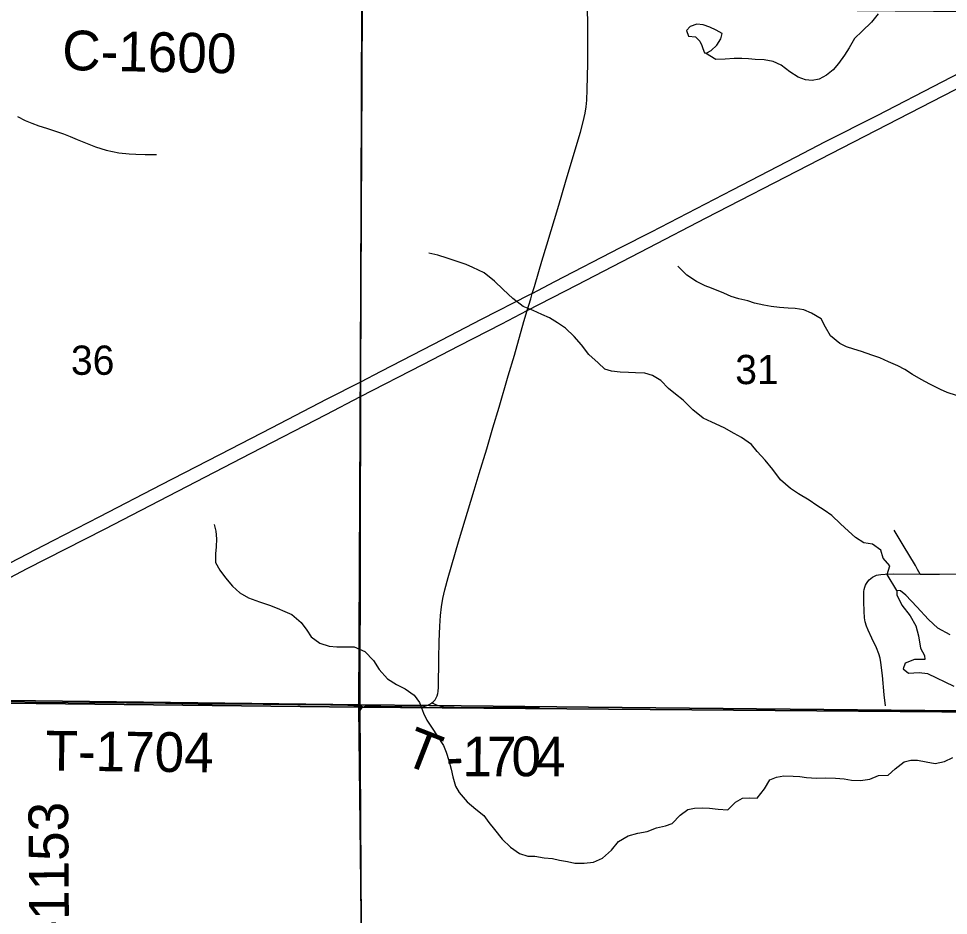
# Model space of a CAD drawing. Extents: x 1874609 to 2204689, y 815661 to 1281160.
# Drawn here: x 2010253 to 2017280, y 1023652 to 1030428 of the extents above; entities that cross this region are included whole.
import ezdxf

# ---------------------------------------------------------------- set-up
doc = ezdxf.new("R2010")
doc.units = 0
for name, color, linetype in [('GM_X_County_Road', 7, 'Continuous'), ('GM_X_County_Road_Text', 7, 'Continuous'), ('GM_X_Interstate_Route', 7, 'Continuous'), ('GM_X_Minor_Lake', 7, 'Continuous'), ('GM_X_Minor_River', 7, 'Continuous'), ('GM_X_Section', 7, 'Continuous'), ('GM_X_Section_Text', 7, 'Continuous'), ('GM_X_Township', 7, 'Continuous'), ('GM_X_Township_Road', 7, 'Continuous'), ('GM_X_Township_Road_Text', 7, 'Continuous')]:
    doc.layers.add(name, color=color, linetype=linetype)

msp = doc.modelspace()

# ---------------------------------------------------------------- linework, layer by layer
at = {"layer": 'GM_X_County_Road'}
for points in [[(2014150.8, 1028403.9), (2014156, 1028421.4), (2014207.7, 1028594.3), (2014246.2, 1028719.7), (2014335.1, 1029018.6), (2014385.5, 1029191.9), (2014452.6, 1029411.5), (2014498.8, 1029569), (2014519.9, 1029648.4), (2014534, 1029712.7), (2014541.5, 1029761.7), (2014546.4, 1029810.8), (2014550.7, 1029893), (2014554.7, 1030089.8), (2014555.1, 1030237.5), (2014554.7, 1030368.4), (2014553, 1030522.7)], [(2013376.8, 1025258.1), (2013389.3, 1025268), (2013400.7, 1025281), (2013409.8, 1025295.5), (2013416.6, 1025311), (2013421.5, 1025327.3), (2013424.6, 1025343.8), (2013427.5, 1025377.1), (2013429.5, 1025590.5), (2013430.8, 1025721.6), (2013435.2, 1025836.2), (2013440.8, 1025917.8), (2013448.4, 1025982.7), (2013459.2, 1026047.1), (2013473.5, 1026110.9), (2013498.9, 1026205.8), (2013577.7, 1026473.3), (2013696.7, 1026865.8), (2013734.3, 1026989.8), (2013790.6, 1027178.3), (2013836.1, 1027335.9), (2013884, 1027492.7), (2013953, 1027729), (2013999.9, 1027886.2), (2014072, 1028138.5), (2014096.4, 1028221.4), (2014122.9, 1028311.5), (2014135.1, 1028352.1), (2014150.8, 1028403.9)], [(2012846.1, 1023532.4), (2012844.1, 1023650.5), (2012841.4, 1023863.8), (2012834.4, 1024421.5), (2012834.6, 1024519.9), (2012832.2, 1024634.9), (2012831.3, 1024716.8), (2012829.1, 1024913.8), (2012828.9, 1024929.4), (2012829.1, 1024977.7), (2012829.3, 1025035), (2012829.5, 1025110.4), (2012829.6, 1025143.3), (2012829.7, 1025155.8), (2012830.1, 1025168), (2012830.8, 1025177.8), (2012832.8, 1025190), (2012834.8, 1025197.9), (2012838.7, 1025207.4), (2012843.4, 1025214.1), (2012850.5, 1025221.6), (2012857.7, 1025226.3)], [(2012857.7, 1025226.3), (2012866.3, 1025230.2), (2012875.8, 1025233), (2012891.5, 1025235.4), (2012908.5, 1025235.1), (2012989.4, 1025233.6), (2013148.3, 1025229.6), (2013264.6, 1025226.6), (2013297.7, 1025228.8), (2013314.3, 1025231.3), (2013330.7, 1025235.1), (2013346.7, 1025240.8), (2013361.8, 1025248.6), (2013375.9, 1025257.4), (2013376.8, 1025258.1)]]:
    msp.add_lwpolyline(points, dxfattribs=at)
at = {"layer": 'GM_X_Interstate_Route'}
for points in [[(2010190.2, 1026315.5), (2010515.5, 1026485.5), (2010865.9, 1026665.1), (2011331.9, 1026907), (2011857.2, 1027177.1), (2012163.3, 1027335.4), (2012586, 1027553.9), (2012838.3, 1027684.6), (2012993.9, 1027765.2), (2013387.8, 1027968), (2013751.6, 1028157.3), (2014117.3, 1028342.8), (2014135.1, 1028352.1), (2014306.6, 1028441.3), (2014801.7, 1028697.7), (2015035.9, 1028816.3), (2015647.3, 1029134), (2016128, 1029383), (2016346.7, 1029495.7), (2016741.2, 1029696.9), (2017236.4, 1029953.7), (2017761.2, 1030224.5)], [(2010189.6, 1026203.8), (2010317.3, 1026271.9), (2010901.7, 1026571), (2012009.6, 1027143.6), (2012578.2, 1027437.4), (2012838, 1027571.5), (2013307.4, 1027813.6), (2013584.1, 1027957.2), (2013905.1, 1028122.6), (2014096.4, 1028221.4), (2014473.5, 1028416.2), (2015012.5, 1028695.3), (2015449.7, 1028921.5), (2016222.7, 1029319.6), (2017753.6, 1030109.5)]]:
    msp.add_lwpolyline(points, dxfattribs=at)
at = {"layer": 'GM_X_Minor_Lake'}
for points in [[(2015453.4, 1030169.6), (2015487.5, 1030187.5), (2015529.8, 1030227.5), (2015560, 1030275.6), (2015570.1, 1030315.7), (2015524.1, 1030341.9), (2015478, 1030364.1), (2015425.9, 1030380.4), (2015379.8, 1030386.5), (2015327.6, 1030368.7), (2015299.4, 1030338.7), (2015315.3, 1030294.5), (2015367.5, 1030290.3), (2015401.5, 1030258.1), (2015415.4, 1030225.9), (2015423.4, 1030201.8)], [(2015423.4, 1030201.8), (2015436.4, 1030169.4), (2015445.8, 1030167.7), (2015453.4, 1030169.6)], [(2017292.7, 1025772.4), (2017198.7, 1025822.9), (2017128.8, 1025887.4), (2017040.9, 1025982.1), (2016959, 1026072.7), (2016917, 1026103), (2016889, 1026107.1), (2016888.9, 1026073), (2016926.7, 1025996.7), (2016990.5, 1025914.1), (2017032.4, 1025839.7), (2017054.1, 1025763.4), (2017069.8, 1025671), (2017099.7, 1025616.7), (2017101.6, 1025584.7), (2017023.4, 1025585), (2016953.2, 1025557.2), (2016939, 1025515.2), (2016979, 1025480.9), (2017059.2, 1025486.5), (2017121.3, 1025480.2), (2017321.4, 1025385.1)]]:
    msp.add_lwpolyline(points, dxfattribs=at)
at = {"layer": 'GM_X_Minor_River'}
for points in [[(2016748, 1030464.1), (2016699.6, 1030400), (2016627.2, 1030332.1), (2016570.9, 1030278.1), (2016528.6, 1030208), (2016494.3, 1030151.9), (2016450, 1030089.9), (2016409.8, 1030039.9), (2016359.5, 1029999.9), (2016303.3, 1029970), (2016251.1, 1029960.2), (2016200.9, 1029964.4), (2016144.8, 1029986.6), (2016080.8, 1030027), (2016016.7, 1030075.4), (2015954.6, 1030103.7), (2015886.5, 1030115.9), (2015820.3, 1030120.2), (2015768.2, 1030124.4), (2015718, 1030126.5), (2015661.9, 1030126.8), (2015591.6, 1030121), (2015523.4, 1030119.2), (2015444.5, 1030167.9)], [(2010244.5, 1029687.2), (2010302.6, 1029658.8), (2010352.6, 1029638.6), (2010406.6, 1029618.3), (2010464.7, 1029600), (2010532.8, 1029577.6), (2010592.9, 1029557.3), (2010642.9, 1029537), (2010694.9, 1029514.7), (2010745, 1029494.4), (2010833.1, 1029459.9), (2010915.2, 1029433.5), (2011011.3, 1029413), (2011089.5, 1029406.6), (2011139.6, 1029404.4), (2011209.7, 1029402.1), (2011295.9, 1029401.7)], [(2016889, 1026107.1), (2016817.3, 1026227.8), (2016837.5, 1026293.9), (2016787.6, 1026350.3), (2016769.8, 1026412.6), (2016705.8, 1026457), (2016641.7, 1026467.3), (2016577.7, 1026507.7), (2016523.8, 1026556.1), (2016463.8, 1026610.5), (2016399.9, 1026673), (2016341.9, 1026713.4), (2016285.9, 1026749.7), (2016227.9, 1026788.1), (2016147.9, 1026836.6), (2016085.9, 1026877), (2016010, 1026943.5), (2015954.1, 1027020), (2015894.2, 1027090.5), (2015834.3, 1027156.9), (2015792.4, 1027209.3), (2015716.4, 1027263.8), (2015660.4, 1027292.1), (2015584.4, 1027336.6), (2015492.3, 1027379.1), (2015426.3, 1027409.5), (2015348.3, 1027472), (2015274.4, 1027544.6), (2015218.5, 1027590.9), (2015164.5, 1027633.3), (2015106.6, 1027693.8), (2015042.6, 1027732.1), (2014986.5, 1027748.4), (2014916.3, 1027750.8), (2014862.2, 1027753), (2014798.1, 1027757.3), (2014734, 1027763.6), (2014683.9, 1027779.9), (2014632, 1027828.2), (2014562, 1027890.7), (2014508.2, 1027963.2), (2014450.3, 1028025.6), (2014386.3, 1028090.1), (2014326.3, 1028130.5), (2014264.3, 1028166.9), (2014206.3, 1028193.2), (2014142.2, 1028221.6), (2014066.2, 1028252), (2013988.2, 1028312.5), (2013914.3, 1028381.1), (2013848.4, 1028443.5), (2013770.4, 1028506.1), (2013686.4, 1028546.6), (2013634.3, 1028568.9), (2013560.2, 1028595.3), (2013492.2, 1028617.7), (2013420.1, 1028640), (2013354, 1028656.4)], [(2015376.2, 1028440.4), (2015302.1, 1028488.8), (2015236.1, 1028557.3)], [(2017341.4, 1027580.9), (2017271.3, 1027603.3), (2017219.2, 1027625.5), (2017139.1, 1027665.9), (2017075, 1027702.3), (2017008.9, 1027738.6), (2016950.8, 1027776.9), (2016898.8, 1027805.2), (2016826.6, 1027833.5), (2016760.5, 1027863.8), (2016700.4, 1027886.1), (2016622.3, 1027912.5), (2016564.2, 1027930.7), (2016510.1, 1027949), (2016460, 1027973.2), (2016387.9, 1028031.7), (2016352, 1028096), (2016318.1, 1028158.3), (2016244, 1028202.7), (2016187.9, 1028227), (2016121.8, 1028237.2), (2016067.6, 1028239.4), (2016003.4, 1028245.7), (2015941.3, 1028253.9), (2015885.2, 1028262.1), (2015815, 1028278.4), (2015762.9, 1028294.6), (2015696.8, 1028310.9), (2015638.6, 1028329.2), (2015582.5, 1028353.4), (2015490.4, 1028391.9), (2015440.3, 1028410.1), (2015376.2, 1028440.4)], [(2011730.9, 1026605.4), (2011742.8, 1026555.2), (2011748.6, 1026497), (2011746.4, 1026436.8), (2011740.2, 1026382.7), (2011741.9, 1026318.5), (2011773.8, 1026260.2), (2011817.7, 1026201.8), (2011869.6, 1026139.4), (2011925.5, 1026089), (2011991.6, 1026050.6), (2012073.6, 1026022.2), (2012149.7, 1025995.7), (2012207.8, 1025973.4), (2012265.8, 1025949.1), (2012317.9, 1025924.8), (2012387.8, 1025864.3), (2012431.7, 1025807.9), (2012463.6, 1025757.7), (2012529.6, 1025709.2), (2012599.6, 1025686.8), (2012657.8, 1025680.6), (2012788.1, 1025680), (2012870.1, 1025645.5), (2012934, 1025577), (2012977.9, 1025508.6), (2013039.8, 1025438.2), (2013109.8, 1025395.7), (2013173.8, 1025363.3), (2013241.8, 1025314.9), (2013281.7, 1025260.6), (2013313.5, 1025180.2), (2013337.3, 1025127.9), (2013377.2, 1025067.6), (2013417.1, 1025009.2), (2013462.9, 1024936.8), (2013484.8, 1024884.6), (2013504.6, 1024822.3), (2013522.4, 1024756), (2013534.2, 1024697.8), (2013554, 1024629.5), (2013581.9, 1024579.2), (2013643.8, 1024510.8), (2013707.8, 1024454.3), (2013767.7, 1024405.9), (2013807.6, 1024353.6), (2013849.5, 1024301.2), (2013907.4, 1024226.8), (2013969.4, 1024168.3), (2014037.3, 1024119.9), (2014101.4, 1024099.5), (2014153.5, 1024099.3), (2014223.6, 1024086.9), (2014287.8, 1024080.6), (2014341.8, 1024068.4), (2014401.9, 1024058.1), (2014456, 1024045.8), (2014526.2, 1024045.5), (2014598.4, 1024055.2), (2014666.6, 1024083), (2014733, 1024144.8), (2014787.4, 1024210.8), (2014859.7, 1024252.6), (2014931.9, 1024272.4), (2015004.1, 1024286.1), (2015074.4, 1024313.8), (2015142.6, 1024327.6), (2015192.8, 1024347.4), (2015253.2, 1024409.3), (2015311.4, 1024453.2), (2015361.6, 1024463), (2015423.7, 1024464.8), (2015473.8, 1024462.5), (2015540, 1024454.2), (2015612.1, 1024449.9), (2015670.5, 1024507.8), (2015722.7, 1024537.6), (2015774.8, 1024541.4), (2015834.9, 1024537.1), (2015889.3, 1024609.1), (2015929.7, 1024675.1), (2015979.9, 1024697), (2016036, 1024706.8), (2016106.2, 1024704.4), (2016156.3, 1024700.2), (2016206.4, 1024694), (2016282.5, 1024689.6), (2016352.7, 1024691.3), (2016426.8, 1024689), (2016493, 1024682.7), (2016547.1, 1024674.4), (2016615.2, 1024670.1), (2016685.4, 1024681.8), (2016751.7, 1024709.6), (2016823.8, 1024711.3), (2016878.1, 1024759.2), (2016944.5, 1024811), (2016996.6, 1024824.8), (2017046.8, 1024824.6), (2017110.9, 1024812.3), (2017179, 1024800)], [(2017179, 1024800), (2017251.2, 1024813.7), (2017313.4, 1024845.5)]]:
    msp.add_lwpolyline(points, dxfattribs=at)
at = {"layer": 'GM_X_Section'}
for points in [[(2012849.2, 1030523), (2012824.4, 1025226.2), (2007499.6, 1025285), (2007548.5, 1030565.7)], [(2018892.4, 1030469.7), (2018801.5, 1025176.8), (2012824.4, 1025226.2), (2012849.2, 1030523)], [(2007373.6, 1025264.7), (2007499.6, 1025285), (2012824.4, 1025226.2), (2012885.7, 1019875.7), (2007432.8, 1019964.2)], [(2012824.4, 1025226.2), (2018801.5, 1025176.8), (2019652, 1025148.6), (2019615.8, 1019513.7), (2012878.4, 1019561.5), (2012885.7, 1019875.7)]]:
    msp.add_lwpolyline(points, close=True, dxfattribs=at)
at = {"layer": 'GM_X_Township'}
for points in [[(2012924.9, 1056002.2), (2012935.3, 1053679.3), (2012914.5, 1051827.7), (2012910.2, 1048822.6), (2012903.7, 1044302.1), (2012899.1, 1041173.4), (2012896.1, 1039044.8), (2012861.2, 1035880.2), (2012864.4, 1032937.1), (2012859.2, 1032479.4), (2012845.9, 1030538.4), (2012837.6, 1027645.9), (2012830.6, 1025241.9), (2010175.8, 1025275.6)], [(2037504.4, 1025002.2), (2030477.9, 1025070.5), (2023338.3, 1025139.8), (2019554.9, 1025176.6), (2018880.2, 1025183.1), (2014559, 1025225.1), (2013359, 1025236.7), (2012830.6, 1025241.9), (2012837.6, 1027645.9), (2012845.9, 1030538.4), (2012859.2, 1032479.4), (2012864.4, 1032937.1), (2012861.2, 1035880.2), (2012896.1, 1039044.8), (2012899.1, 1041173.4), (2012903.7, 1044302.1), (2012910.2, 1048822.6), (2012914.5, 1051827.7), (2012935.3, 1053679.3), (2012924.9, 1056002.2)], [(1993938.6, 1022996.1), (1993885.9, 1025282.7), (1999244.1, 1025264.8), (2003309.4, 1025289.7), (2006858, 1025283.1), (2007779, 1025268.2), (2008456.2, 1025273.8), (2008788.6, 1025279.1), (2010175.8, 1025275.6), (2012830.6, 1025241.9), (2012842.5, 1023547.9)], [(2013012.1, 995874.2), (2012966.8, 1001159.1), (2012977.9, 1002278.3), (2012961.7, 1005114.1), (2012927.2, 1008777.9), (2012920.4, 1010262.3), (2012905.6, 1014235.6), (2012905.1, 1014538.5), (2012901.8, 1015157.2), (2012859.4, 1019535.5), (2012856.4, 1019843.6), (2012864.5, 1022216.8), (2012842.5, 1023547.9), (2012830.6, 1025241.9), (2013359, 1025236.7), (2014559, 1025225.1), (2018880.2, 1025183.1), (2019554.9, 1025176.6), (2023338.3, 1025139.8), (2030477.9, 1025070.5), (2037504.4, 1025002.2)]]:
    msp.add_lwpolyline(points, dxfattribs=at)
at = {"layer": 'GM_X_Township_Road'}
for points in [[(2017065.5, 1026230.9), (2017046.5, 1026266.3), (2017030.9, 1026295.2), (2016938.6, 1026450.3), (2016870.3, 1026562.4)], [(2016805.4, 1025236.4), (2016795, 1025318), (2016781.2, 1025465.4), (2016770.2, 1025563.4), (2016764.2, 1025595.7), (2016754.9, 1025627.2), (2016736.3, 1025672.9), (2016700.7, 1025747), (2016672.8, 1025806.6), (2016661, 1025837.3), (2016651.9, 1025868.9), (2016646.3, 1025901.3), (2016642.8, 1025950.5), (2016641.5, 1026022), (2016640.4, 1026082), (2016641.2, 1026098.4), (2016643.4, 1026114.7), (2016647.4, 1026130.7), (2016653.1, 1026146), (2016660.8, 1026160.6), (2016670.2, 1026174), (2016681.3, 1026186.2), (2016693.6, 1026197.1), (2016707, 1026206.8), (2016721.1, 1026215), (2016736.2, 1026221.6), (2016751.8, 1026226.1), (2016768.1, 1026228.9), (2016800.9, 1026231.3), (2016866.7, 1026232.6), (2017065.5, 1026230.9)], [(2017065.5, 1026230.9), (2017097, 1026230.6), (2017212.1, 1026231.3), (2017343.6, 1026231.9), (2017383.2, 1026232.1)], [(2010169.6, 1025267.4), (2010218.2, 1025267.4), (2010381.9, 1025263.6), (2010627.5, 1025261.4), (2011069.6, 1025257), (2011364.4, 1025254.6), (2011610, 1025251.2), (2011790.1, 1025249.6), (2012101.3, 1025247.6), (2012363.3, 1025245), (2012608.9, 1025242.1), (2012739.9, 1025239.5), (2012829.3, 1025236.5), (2012838.3, 1025235), (2012845, 1025233), (2012857.7, 1025226.3)], [(2013376.8, 1025258.1), (2013417.4, 1025241), (2013432.8, 1025235.6), (2013448, 1025231), (2013464.2, 1025228.4), (2013496.8, 1025225.9), (2013545.9, 1025225.4), (2013791.7, 1025223), (2013971.4, 1025222.5), (2014003.5, 1025223.4), (2014042.4, 1025223.3), (2014084.6, 1025223.1), (2014143.6, 1025222.9), (2014188.6, 1025222.7)]]:
    msp.add_lwpolyline(points, dxfattribs=at)

# ---------------------------------------------------------------- texts
at = {"layer": 'GM_X_County_Road_Text'}
msp.add_text('C-1600', height=300, rotation=358.85367, dxfattribs=at).set_placement((2010580.5, 1030039.8))
at = {"layer": 'GM_X_Section_Text'}
for s, p in [('36', (2010648.4, 1027736.5)), ('31', (2015668.7, 1027666.1))]:
    msp.add_text(s, height=221, rotation=0.00001, dxfattribs=at).set_placement(p)
at = {"layer": 'GM_X_Township_Road_Text'}
for s, rotation, p in [('T', 338.7151, (2013145, 1024802)), ('T-1704', 359.29517, (2010454.7, 1024747.2)), ('1', 359.76582, (2013606.7, 1024704)), ('7', 359.93879, (2013792.5, 1024703.3)), ('0', 359.98795, (2013977.6, 1024703.1)), ('4', 359.99915, (2014162.4, 1024703)), ('-', 2.58003, (2013487.5, 1024698.6)), ('T-1153', 90.46678, (2010636.7, 1023239.4))]:
    msp.add_text(s, height=300, rotation=rotation, dxfattribs=at).set_placement(p)

doc.saveas('drawing.dxf')
